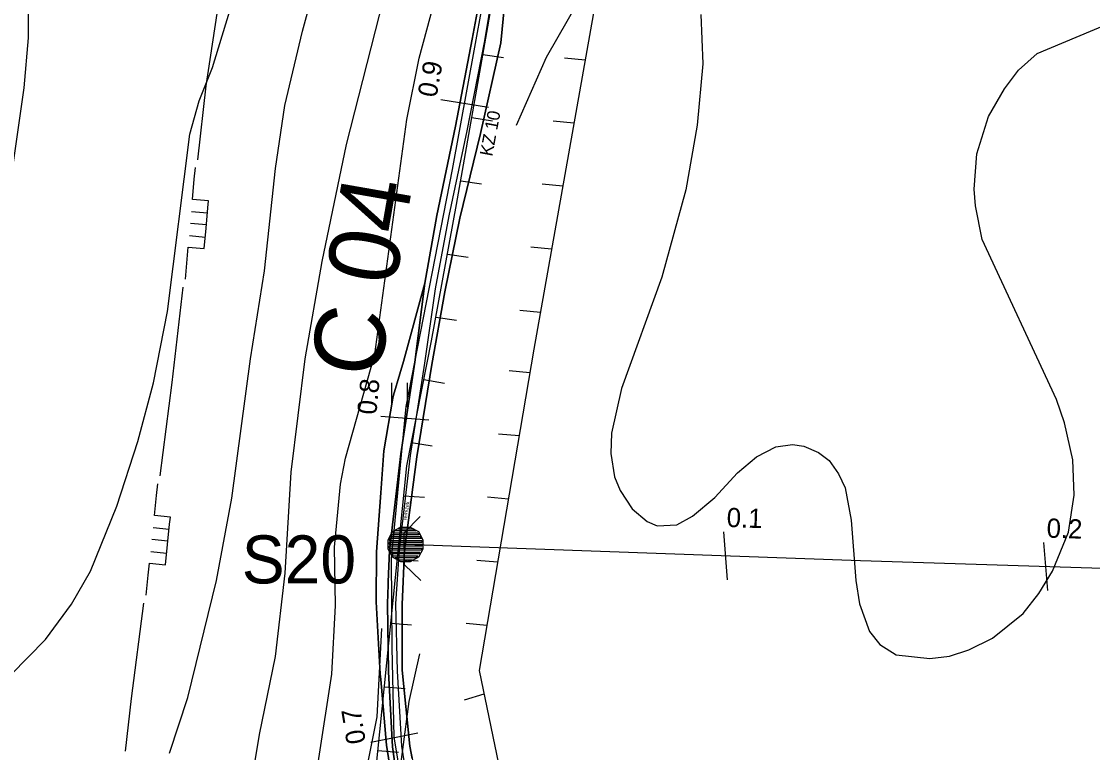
# Model space of a CAD drawing. Extents: x -645676 to -642474, y -1077513 to -1072613.
# Drawn here: x -644258.9 to -643924.4, y -1076481.9 to -1076253.6 of the extents above; entities that cross this region are included whole.
import ezdxf

# ---------------------------------------------------------------- set-up
doc = ezdxf.new("R2010")
doc.units = 0
for name, color, linetype in [('KRAJ_ZELEN_STAV', 7, 'Continuous'), ('Krajinn__zele____popis___stav', 7, 'Continuous'), ('KULTURY_STAV', 7, 'Continuous'), ('KULTURY_ZNACKY', 7, 'Continuous'), ('PC_NAVRH', 7, 'Continuous'), ('PC_OBJ_POPIS_NAVRH', 7, 'Continuous'), ('PC_OBJEKTY_NAVRH', 7, 'Continuous'), ('PC_POPIS_NAVRH', 7, 'Continuous'), ('PC_STAN_NAVRH', 7, 'Continuous'), ('PLYNOVOD', 7, 'Continuous'), ('USES_BK_NAVRH', 7, 'Continuous'), ('VRSTEVNICE', 7, 'Continuous')]:
    doc.layers.add(name, color=color, linetype=linetype)

# ---------------------------------------------------------------- blocks, each defined once
blk = doc.blocks.new('$406')
blk.add_lwpolyline([(-0.19, 0.72), (0.2, 0.72), (0.54, 0.53), (0.73, 0.19), (0.73, -0.2), (0.54, -0.54), (0.2, -0.73), (-0.19, -0.73), (-0.53, -0.54), (-0.72, -0.2), (-0.72, 0.19), (-0.53, 0.53), (-0.2, 0.72), (-0.28, 0.64), (0.28, 0.64), (0.44, 0.56), (-0.44, 0.56), (-0.52, 0.48), (0.52, 0.48), (0.56, 0.4), (-0.55, 0.4), (-0.6, 0.32), (0.6, 0.32), (0.68, 0.24), (-0.59, 0.24), (-0.65, 0.24), (-0.68, 0.16), (0.59, 0.16), (0.68, 0.16), (0.68, 0.08), (-0.59, 0.08), (-0.68, 0.08), (-0.68, 0), (0.59, 0), (0.68, 0), (0.68, -0.08), (-0.59, -0.08), (-0.68, -0.08), (-0.68, -0.16), (0.59, -0.16), (0.68, -0.16), (0.65, -0.24), (-0.62, -0.24), (-0.65, -0.24), (-0.6, -0.32), (0.6, -0.32), (0.56, -0.4), (-0.55, -0.4), (-0.52, -0.48), (0.52, -0.48), (0.44, -0.56), (-0.44, -0.56), (-0.28, -0.64), (0.28, -0.64), (-0.02, -0.69)])
blk = doc.blocks.new('$944')
blk.add_line((0, 1.5), (0, -1.5))
blk = doc.blocks.new('3$0600')
for p, q in [((-0.5, 1.5), (-0.5, 0)), ((0.5, 0), (0.5, 1.5))]:
    blk.add_line(p, q)
blk = doc.blocks.new('$935')
blk.add_lwpolyline([(-2, -1), (-1, 0), (1, 0), (2, -1)])
blk = doc.blocks.new('2$1030')
blk.add_line((0, 0), (0, -0.5))
blk = doc.blocks.new('6$3520')
for p, q in [((-0.76, 0), (-0.76, -1)), ((0, -1), (0, 0)), ((0.76, 0), (0.76, -1))]:
    blk.add_line(p, q)
blk.add_lwpolyline([(-3.5, 0), (-2.23, 0), (-1.48, 0), (-1.48, -1), (-0.21, -1), (1.06, -1), (1.5, -1), (1.5, 0), (2.77, 0), (3.5, 0)])

msp = doc.modelspace()

# ---------------------------------------------------------------- linework, layer by layer
at = {"layer": 'KRAJ_ZELEN_STAV'}
for points in [[(-644106.22, -1076229.19), (-644109.17, -1076260.32), (-644115.54, -1076288.59), (-644122.04, -1076314.98), (-644126.64, -1076338.06), (-644130.75, -1076360.67), (-644135.42, -1076389.52), (-644139.33, -1076418.74), (-644140.05, -1076435.63), (-644139.97, -1076456.12), (-644137.6, -1076479.83), (-644133.96, -1076498.84)], [(-644132.92, -1076360.25), (-644129.57, -1076337.09), (-644125.36, -1076314.27), (-644119.7, -1076287.78), (-644114.19, -1076259.66), (-644109.1, -1076228.56)], [(-644136.73, -1076500.7), (-644140.1, -1076479.81), (-644141.48, -1076456.39), (-644141.98, -1076435.39), (-644140.81, -1076418.41), (-644137.44, -1076389.13), (-644132.92, -1076360.25)]]:
    msp.add_lwpolyline(points, dxfattribs=at)
at = {"layer": 'KULTURY_STAV'}
for points in [[(-644112.19, -1076227.42), (-644118.1, -1076259.16), (-644123.39, -1076286.31), (-644129.18, -1076314.19), (-644132.91, -1076335.29), (-644139.6, -1076359.74), (-644140.74, -1076363.63), (-644142.67, -1076370.24), (-644142.96, -1076371.24), (-644145.76, -1076387.62), (-644146.7, -1076400.75), (-644148.02, -1076419.16), (-644148.09, -1076434.84), (-644146.85, -1076457.24), (-644146.69, -1076459.04), (-644144.9, -1076479.52), (-644143.93, -1076485.51)], [(-644139.88, -1076502.73), (-644143.01, -1076480.06), (-644144.28, -1076456.67), (-644144.62, -1076435.29), (-644144.38, -1076429.53), (-644144.34, -1076428.52), (-644143.93, -1076418.72), (-644140.45, -1076388.54), (-644136.1, -1076360.01), (-644132.91, -1076335.29), (-644129.18, -1076314.19), (-644123.39, -1076286.31), (-644118.1, -1076259.16), (-644112.19, -1076227.42)], [(-644106.22, -1076229.19), (-644109.17, -1076260.32), (-644115.54, -1076288.59), (-644122.04, -1076314.98), (-644126.64, -1076338.06), (-644130.75, -1076360.67), (-644135.42, -1076389.52), (-644139.33, -1076418.74), (-644140.05, -1076435.63), (-644139.97, -1076456.12), (-644137.6, -1076479.83), (-644136.86, -1076483.71)], [(-644136.86, -1076483.71), (-644137.6, -1076479.83), (-644139.97, -1076456.12), (-644140.05, -1076435.63), (-644139.33, -1076418.74), (-644135.42, -1076389.52), (-644130.75, -1076360.67), (-644126.64, -1076338.06), (-644122.04, -1076314.98), (-644115.54, -1076288.59), (-644109.17, -1076260.32), (-644106.22, -1076229.19)], [(-644143.93, -1076485.51), (-644144.9, -1076479.52), (-644146.69, -1076459.04), (-644146.85, -1076457.24), (-644148.09, -1076434.84), (-644148.02, -1076419.16), (-644146.7, -1076400.75), (-644145.76, -1076387.62), (-644142.96, -1076371.24), (-644142.67, -1076370.24), (-644140.74, -1076363.63), (-644139.6, -1076359.74), (-644132.91, -1076335.29)], [(-644132.91, -1076335.29), (-644136.1, -1076360.01), (-644140.45, -1076388.54), (-644143.93, -1076418.72), (-644144.34, -1076428.52), (-644144.38, -1076429.53), (-644144.62, -1076435.29), (-644144.28, -1076456.67), (-644143.01, -1076480.06), (-644139.88, -1076502.73)]]:
    msp.add_lwpolyline(points, dxfattribs=at)
at = {"layer": 'PC_NAVRH'}
for points in [[(-644139.39, -1076495.57), (-644142.46, -1076477.03), (-644143.16, -1076449.01), (-644143.37, -1076421.26), (-644138.79, -1076373.8), (-644124.24, -1076299.79), (-644107.91, -1076210.28), (-644099.52, -1076165.84)], [(-644139, -1076416.84), (-643996.94, -1076421.9), (-643507.65, -1076437.43), (-643217.45, -1076446.55)]]:
    msp.add_lwpolyline(points, dxfattribs=at)
at = {"layer": 'PLYNOVOD'}
for points in [[(-644203.86, -1076296.81), (-644201.22, -1076273.74), (-644191.65, -1076210.65), (-644179.98, -1076144.48), (-644173.75, -1076115.13)], [(-644215.57, -1076395.51), (-644211.8, -1076366.36), (-644208.4, -1076336.55)], [(-644226.44, -1076481.43), (-644224.55, -1076464.93), (-644220.7, -1076435.18)]]:
    msp.add_lwpolyline(points, dxfattribs=at)
at = {"layer": 'USES_BK_NAVRH'}
for points in [[(-644001.62, -1075978.91), (-644033.51, -1076072.43), (-644043.56, -1076115.08), (-644055.98, -1076162.98), (-644067.17, -1076183.7), (-644078.1, -1076238.58), (-644098.86, -1076355.9), (-644115.99, -1076456.27), (-644109.33, -1076488.41)], [(-644148.37, -1076488.7), (-644138.52, -1076392.37), (-644130.82, -1076353.27), (-644122.99, -1076310.72), (-644109.72, -1076235.13), (-644096.83, -1076166.36), (-644093.66, -1076163), (-644087.08, -1076155.79), (-644082.23, -1076149.72), (-644076.69, -1076131.48), (-644072.64, -1076111.89), (-644068.4, -1076092.44), (-644058.62, -1076060.2), (-644047.3, -1076015.73)]]:
    msp.add_lwpolyline(points, dxfattribs=at)
at = {"layer": 'VRSTEVNICE'}
for points in [[(-644262.24, -1076457.55), (-644251.38, -1076446.55), (-644243.27, -1076435.54), (-644237.33, -1076425.26), (-644229.07, -1076404.98), (-644222.56, -1076384.71), (-644217.63, -1076366.46), (-644213.29, -1076344.16), (-644206.34, -1076288.84), (-644203.44, -1076278.41), (-644199.24, -1076267.98), (-644193.88, -1076250.61), (-644189.97, -1076232.65), (-644187.51, -1076210.35), (-644187.51, -1076193.84), (-644186.5, -1076176.46), (-644181.28, -1076149.52), (-644179.54, -1076131.27), (-644179.69, -1076119.4), (-644182.01, -1076099.99), (-644186.93, -1076077.4), (-644189.54, -1076064.08), (-644195.62, -1076029.32)], [(-644212.71, -1076482.03), (-644206.92, -1076464.65), (-644197.94, -1076428.16), (-644193.16, -1076402.38), (-644187.36, -1076358.93), (-644183.02, -1076331.42), (-644179.54, -1076299.55), (-644176.65, -1076279.86), (-644171.14, -1076256.69), (-644164.05, -1076230.62), (-644161.15, -1076214.98), (-644159.99, -1076202.81), (-644158.54, -1076169.79), (-644156.95, -1076164.73), (-644152.32, -1076162.41), (-644149.42, -1076157.92), (-644149.42, -1076149.23), (-644150.15, -1076144.89), (-644151.74, -1076141.99), (-644160.87, -1076134.82), (-644167.24, -1076116)], [(-644127.07, -1076146.07), (-644128.96, -1076152.26), (-644129.15, -1076155.6), (-644130.45, -1076160.53), (-644134.79, -1076164.58), (-644144.5, -1076171.24), (-644146.52, -1076175.44), (-644146.38, -1076182.54), (-644141.46, -1076205.13), (-644141.02, -1076215.56), (-644141.46, -1076224.25), (-644143.34, -1076236.41), (-644157.53, -1076292.02), (-644165.06, -1076328.52), (-644170.42, -1076358.93), (-644174.76, -1076394.27), (-644176.65, -1076425.84), (-644179.69, -1076451.91), (-644184.61, -1076476.24), (-644192.14, -1076521.42)], [(-644160.86, -1076435.98), (-644161.15, -1076417.73), (-644159.27, -1076398.03), (-644157.68, -1076389.92), (-644148.55, -1076357.48), (-644138.56, -1076284.2), (-644134.65, -1076265.09), (-644129.87, -1076247.42), (-644126.97, -1076233.23), (-644126.39, -1076218.46), (-644127.26, -1076210.35), (-644130.3, -1076196.15), (-644131.32, -1076188.04), (-644130.59, -1076175.88), (-644129.29, -1076171.82), (-644126.97, -1076167.77), (-644123.35, -1076163.86), (-644117.25, -1076159.47)], [(-644262.53, -1076305.64), (-644258.04, -1076274.36), (-644256.73, -1076258.72), (-644256.59, -1076242.78), (-644257.89, -1076226.27), (-644263.25, -1076198.76)], [(-644104.33, -1076285.96), (-644094.97, -1076264.8), (-644084.83, -1076247.13)], [(-644046.74, -1076251.47), (-644046.16, -1076266.83), (-644047.9, -1076285.94), (-644051.38, -1076306.22), (-644058.91, -1076333.44), (-644071.51, -1076368.2), (-644074.69, -1076382.1), (-644074.84, -1076388.48), (-644073.68, -1076395.72), (-644071.94, -1076400.06), (-644068.18, -1076405.71), (-644063.54, -1076409.76), (-644060.36, -1076411.07), (-644054.27, -1076410.78), (-644049.35, -1076408.02), (-644042.4, -1076402.23), (-644035.3, -1076394.56), (-644029.36, -1076389.49), (-644023.28, -1076386.45), (-644018.07, -1076385.72), (-644014.59, -1076386.16), (-644009.96, -1076388.19), (-644006.63, -1076390.65), (-644003.73, -1076394.85), (-644001.7, -1076399.19), (-643999.82, -1076409.33), (-643998.37, -1076428.16), (-643997.21, -1076435.4), (-643994.03, -1076444.09), (-643990.84, -1076448.14), (-643985.77, -1076451.33), (-643975.2, -1076452.49), (-643969.12, -1076451.76), (-643963.04, -1076449.73), (-643955.65, -1076446.11), (-643946.09, -1076438.44), (-643941.17, -1076432.21), (-643936.97, -1076425.26), (-643931.9, -1076413.09), (-643930.16, -1076401.51)], [(-643930.16, -1076401.51), (-643930.6, -1076390.5), (-643933.2, -1076378.92), (-643935.66, -1076371.68), (-643958.89, -1076321.64), (-643961.01, -1076311.14), (-643961.44, -1076305.93), (-643960.57, -1076294.92), (-643956.95, -1076283.33), (-643951.89, -1076274.65), (-643947.54, -1076268.85), (-643941.75, -1076263.64), (-643920.6, -1076254.8)], [(-644169.84, -1076508.68), (-644162.02, -1076457.41), (-644160.86, -1076435.98)], [(-644248.33, -1076752.41), (-644240.22, -1076754.15), (-644232.11, -1076754.44), (-644223.43, -1076752.7), (-644214.74, -1076748.65), (-644207.78, -1076743.58), (-644201.7, -1076737.06), (-644196.49, -1076729.09), (-644192.14, -1076720.7), (-644186.21, -1076706.79), (-644183.02, -1076697.52), (-644172.3, -1076649.73), (-644155.94, -1076545.46), (-644154.2, -1076523.74), (-644154.06, -1076506.36), (-644153.19, -1076497.67), (-644147.83, -1076470.73), (-644146.38, -1076443.07)], [(-644141.75, -1076495.93), (-644137.84, -1076465.95), (-644134.48, -1076450.98)]]:
    msp.add_lwpolyline(points, dxfattribs=at)

# ---------------------------------------------------------------- block references
at = {"layer": 'KULTURY_ZNACKY', "xscale": 5, "yscale": 5}
msp.add_blockref('3$0600', (-644140.82, -1076373.92), dxfattribs=at)
at = {"layer": 'PC_OBJEKTY_NAVRH', "xscale": 5, "yscale": 4.999999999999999, "rotation": 90.64993400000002}
msp.add_blockref('$935', (-644139.3, -1076418.21), dxfattribs=at)
at = {"layer": 'PC_STAN_NAVRH'}
for p, xscale, yscale, rotation in [((-644120.48, -1076279.18), 5, 5.000000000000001, 81.060278), ((-644139.14, -1076377.4), 4.999999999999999, 5.000000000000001, 85.962954), ((-644039.07, -1076420.4), 5, 5, 4.208717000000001), ((-643939.12, -1076423.74), 5, 4.999999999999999, 4.436073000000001), ((-644142.43, -1076477.19), 5, 5, 101.149009)]:
    msp.add_blockref('$944', p, dxfattribs=dict(at, xscale=xscale, yscale=yscale, rotation=rotation))
at = {"layer": 'PC_STAN_NAVRH', "xscale": 7.5, "yscale": 7.5}
msp.add_blockref('$406', (-644139, -1076416.84), dxfattribs=at)
at = {"layer": 'PLYNOVOD', "xscale": 5}
for p, yscale, rotation in [((-644206.13, -1076316.68), 4.999999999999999, 84.940399), ((-644218.14, -1076415.34), 5, 84.071891)]:
    msp.add_blockref('6$3520', p, dxfattribs=dict(at, yscale=yscale, rotation=rotation))
at = {"layer": 'USES_BK_NAVRH'}
for p, xscale, yscale, rotation in [((-644114.78, -1076263.94), 12.999999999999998, 13.000000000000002, 81.439222), ((-644082.89, -1076265.66), 12.999999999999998, 13.000000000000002, -95.495526), ((-644118.24, -1076283.63), 12.999999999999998, 13.000000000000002, 81.439222), ((-644086.38, -1076285.35), 12.999999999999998, 13.000000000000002, -95.495526), ((-644121.7, -1076303.33), 12.999999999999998, 13.000000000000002, 81.439222), ((-644089.86, -1076305.04), 12.999999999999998, 13.000000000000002, -95.495526), ((-644093.34, -1076324.74), 12.999999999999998, 13.000000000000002, -95.495526), ((-644125.85, -1076326.22), 13.000000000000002, 13, 80.963605), ((-644096.83, -1076344.43), 12.999999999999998, 13.000000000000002, -95.495526), ((-644129.47, -1076345.89), 13.000000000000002, 13, 80.963605), ((-644100.12, -1076363.3), 12.999999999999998, 13.000000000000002, -95.14163500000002), ((-644133.21, -1076365.39), 13.000000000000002, 13, 80.24651099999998), ((-644103.48, -1076383.01), 12.999999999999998, 13.000000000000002, -95.14163500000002), ((-644137.07, -1076385.01), 13.000000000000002, 13, 80.24651099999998), ((-644139.47, -1076401.66), 13, 13.000000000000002, 85.627166), ((-644106.85, -1076402.72), 12.999999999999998, 13.000000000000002, -95.14163500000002), ((-644141.5, -1076421.55), 13, 13.000000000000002, 85.627166), ((-644110.21, -1076422.44), 12.999999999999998, 13.000000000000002, -95.14163500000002), ((-644143.54, -1076441.45), 13, 13.000000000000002, 85.627166), ((-644113.58, -1076442.15), 12.999999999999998, 13.000000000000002, -95.14163500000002), ((-644145.57, -1076461.35), 13, 13.000000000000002, 85.627166), ((-644114.47, -1076463.62), 13, 12.999999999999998, -73.37748100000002), ((-644147.61, -1076481.24), 13, 13.000000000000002, 85.627166)]:
    msp.add_blockref('2$1030', p, dxfattribs=dict(at, xscale=xscale, yscale=yscale, rotation=rotation))

# ---------------------------------------------------------------- texts
at = {"layer": 'Krajinn__zele____popis___stav'}
for s, height, rotation, p in [('KZ 10', 4, 79.412, (-644111.88, -1076295.9)), ('remízek', 1.2, 81.016, (-644138.61, -1076409.37))]:
    msp.add_text(s, height=height, rotation=rotation, dxfattribs=at).set_placement(p)
at = {"layer": 'PC_OBJ_POPIS_NAVRH'}
msp.add_text('S20', height=15, dxfattribs=at).set_placement((-644190.09, -1076429.05))
at = {"layer": 'PC_POPIS_NAVRH'}
msp.add_text('C 04', height=22, rotation=80.099, dxfattribs=at).set_placement((-644147.36, -1076365.61))
at = {"layer": 'PC_STAN_NAVRH'}
for s, rotation, p in [('0.9', 79.641, (-644129.33, -1076277.57)), ('0.8', 84.511, (-644148.1, -1076376.54)), ('0.1', 357.984, (-644038.75, -1076411.41)), ('0.2', 358.213, (-643938.84, -1076414.74)), ('0.7', 99.408, (-644151.31, -1076478.67))]:
    msp.add_text(s, height=6, rotation=rotation, dxfattribs=at).set_placement(p)

doc.saveas('drawing.dxf')
